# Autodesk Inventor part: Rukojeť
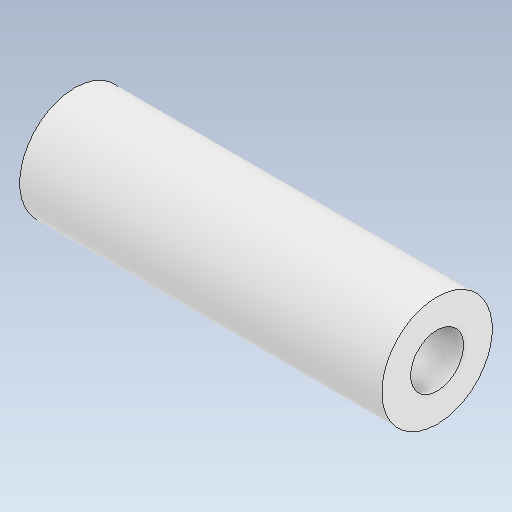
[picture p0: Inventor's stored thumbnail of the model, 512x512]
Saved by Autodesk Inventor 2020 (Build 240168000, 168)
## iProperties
Created: 2025-03
Part Number: Rukojeť
Material: PVC potrubí
Document SubType Name: Modeling
Designer: doma
Density: 1.4 g/cm^3
Appearance: Hladká – bílá
Mass: 40.9772 g
Surface Area: 105.228 cm^2
Volume: 29.2694 cm^3
Author: doma
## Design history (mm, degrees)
sketch "Náčrt1"
  geometry: L1 (0, 0)-(0, 12.5); L2 (0, 12.5)-(82, 12.5); L3 (82, 12.5)-(82, 0); L4 (82, 0)-(0, 0); L5 (82, 6)-(15, 6); L6 (15, 6)-(15, 8.5); L7 (15, 8.5)-(0, 8.5)
  constraints: 14 end point, 4 perpendicular, 2 horizontal, 2 point on line, 1 vertical
  dimensions: "d0" = 12.5 distance of L1.start L1.end; "d1" = 82 distance of L1.end L2.end; "d3" = 8.5 distance between parallel lines of L4 L7; "d4" = 6 distance between parallel lines of L4 L5; "d5" = 15 distance of L6.end L7.end
revolve "Rotace1" sketch "Náčrt1" stored, may be unused: angle "d6" = 90 deg
node "Těleso1"
